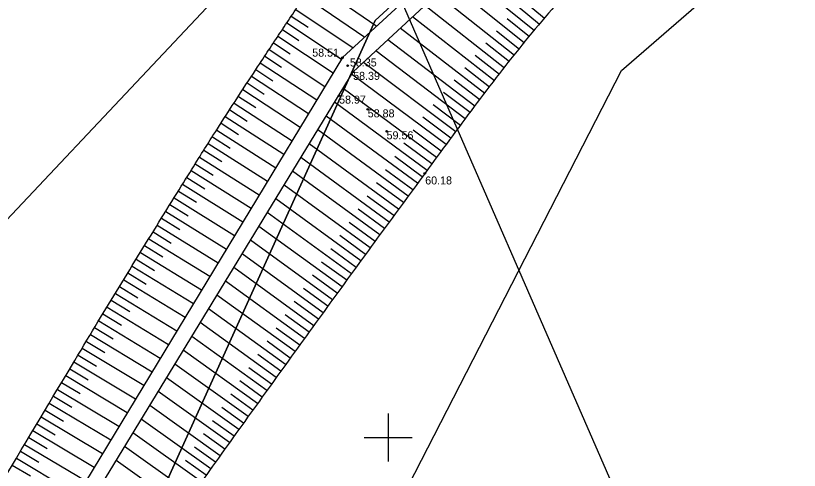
# Model space of a CAD drawing. Extents: x 616607 to 617499, y 408385 to 409695.
# Drawn here: x 616976.74 to 617025.68, y 408647.94 to 408676.32 of the extents above; entities that cross this region are included whole.
import ezdxf

# ---------------------------------------------------------------- set-up
doc = ezdxf.new("R2010")
doc.units = 0
for name, color, linetype in [('GEOD_ELEM_####_####_#', 7, 'Continuous'), ('HIDG_GRAV_####_####_#', 7, 'Continuous'), ('RAMI_PLAN_####_TKST_#', 7, 'Continuous'), ('RAMI_UZMR_####_####_#', 7, 'Continuous'), ('RELJ_AATZ_####_TKST_#', 7, 'Continuous'), ('RELJ_ELEM_####_####_#', 7, 'Continuous'), ('RELJ_NOGA_####_####_#', 7, 'Continuous'), ('ROBZ_IERR_####_####_#', 7, 'Continuous')]:
    doc.layers.add(name, color=color, linetype=linetype)

# ---------------------------------------------------------------- blocks, each defined once
blk = doc.blocks.new('PKT')
at = {"layer": 'RELJ_ELEM_####_####_#'}
blk.add_circle((0, 0), 0.05, dxfattribs=at)
blk = doc.blocks.new('KRUSTS')
at = {"layer": 'GEOD_ELEM_####_####_#'}
for p, q in [((0, 1.5), (0, 0)), ((-1.5, 0), (0, 0)), ((0, 0), (0, -1.5)), ((0, 0), (1.5, 0))]:
    blk.add_line(p, q, dxfattribs=at)

msp = doc.modelspace()

# ---------------------------------------------------------------- linework, layer by layer
at = {"layer": 'HIDG_GRAV_####_####_#'}
msp.add_lwpolyline([(616957.708, 408604.801), (616964.717, 408618.582), (616997.814, 408672.816), (617082.506, 408751.106), (617088.497, 408760.889), (617116.937, 408835.934), (617137.451, 408884.548), (617152.78, 408924.733), (617163.79, 408955.542), (617160.997, 408956.152), (617115.742, 408836.043), (617088.001, 408760.943), (617081.506, 408751.106), (616997.147, 408673.705), (616963.717, 408618.582), (616956.708, 408604.801)], dxfattribs=at)
at = {"layer": 'RAMI_PLAN_####_TKST_#'}
msp.add_line((616996.579, 408686.958), (617053.954, 408555.52), dxfattribs=at)
at = {"layer": 'RAMI_UZMR_####_####_#'}
for points in [[(617191.828, 409115.62), (617145.545, 408952.8), (617072.809, 408766.141), (616965.332, 408652.076), (616939.432, 408594.661), (616924.839, 408592.467), (616706.433, 408526.081), (616666.426, 408467.691)], [(616666.426, 408467.691), (616675.529, 408457.882), (616687.228, 408463.356), (616723.888, 408465.775), (616753.554, 408507.232), (616948.282, 408568.831), (616981.528, 408608.531), (617014.563, 408672.892), (617101.571, 408748.246), (617213.472, 409074.039)]]:
    msp.add_lwpolyline(points, dxfattribs=at)
at = {"layer": 'RELJ_NOGA_####_####_#'}
for p, q in [((617009.774, 408676.155), (617005.373, 408679.803)), ((617009.139, 408675.383), (617004.6, 408679.089)), ((616995.351, 408678.366), (616999.291, 408675.672)), ((617008.508, 408674.607), (617003.83, 408678.377)), ((616994.788, 408677.54), (616998.55, 408674.991)), ((617007.883, 408673.827), (617003.063, 408677.667)), ((616994.229, 408676.711), (616997.806, 408674.309)), ((617007.262, 408673.043), (617002.294, 408676.957)), ((617009.456, 408675.77), (617008.117, 408676.874)), ((616993.861, 408676.16), (616993.862, 408676.159)), ((616993.951, 408676.295), (616994.996, 408675.597)), ((617006.645, 408672.256), (617001.524, 408676.245)), ((617008.823, 408674.996), (617007.442, 408676.118)), ((616993.584, 408675.744), (616993.584, 408675.744)), ((616993.674, 408675.879), (616997.087, 408673.606)), ((616993.307, 408675.328), (616993.308, 408675.327)), ((616993.397, 408675.463), (616994.426, 408674.777)), ((617006.033, 408671.465), (617000.758, 408675.537)), ((617008.195, 408674.217), (617006.772, 408675.36)), ((616992.843, 408674.63), (616993.883, 408673.939)), ((616993.03, 408674.912), (616993.03, 408674.911)), ((616993.12, 408675.047), (616996.568, 408672.75)), ((617005.424, 408670.672), (616999.987, 408674.824)), ((617007.572, 408673.435), (617006.103, 408674.598)), ((616992.566, 408674.214), (616996.054, 408671.903)), ((616992.753, 408674.495), (616992.754, 408674.495)), ((617004.819, 408669.876), (616999.223, 408674.118)), ((616992.201, 408673.661), (616992.202, 408673.661)), ((616992.29, 408673.797), (616993.343, 408673.102)), ((616992.477, 408674.078), (616992.477, 408674.078)), ((617006.953, 408672.65), (617005.44, 408673.835)), ((616991.926, 408673.244), (616991.926, 408673.244)), ((616992.015, 408673.379), (616995.543, 408671.06)), ((617004.217, 408669.077), (616998.454, 408673.407)), ((616991.652, 408672.826), (616991.653, 408672.825)), ((616991.741, 408672.961), (616992.805, 408672.265)), ((617003.618, 408668.276), (616997.721, 408672.664)), ((617006.338, 408671.861), (617004.779, 408673.07)), ((616991.193, 408672.124), (616992.267, 408671.424)), ((616991.378, 408672.407), (616991.378, 408672.407)), ((616991.467, 408672.543), (616995.028, 408670.211)), ((617005.728, 408671.069), (617004.12, 408672.301)), ((616990.92, 408671.706), (616994.513, 408669.362)), ((616991.105, 408671.988), (616991.106, 408671.988)), ((617003.022, 408667.473), (616997.184, 408671.784)), ((616990.559, 408671.15), (616990.56, 408671.15)), ((616990.648, 408671.286), (616991.731, 408670.583)), ((616990.832, 408671.57), (616990.832, 408671.569)), ((617005.121, 408670.274), (617003.463, 408671.531)), ((616990.288, 408670.731), (616990.288, 408670.73)), ((616990.376, 408670.867), (616994.002, 408668.518)), ((617002.429, 408666.668), (616996.654, 408670.914)), ((617004.517, 408669.477), (617002.814, 408670.762)), ((616990.016, 408670.311), (616990.017, 408670.31)), ((616990.104, 408670.447), (616991.197, 408669.742)), ((616989.745, 408669.89), (616989.746, 408669.89)), ((616989.833, 408670.027), (616993.49, 408667.674)), ((617001.838, 408665.862), (616996.126, 408670.05)), ((617003.917, 408668.677), (617002.161, 408669.988)), ((616989.475, 408669.469), (616989.476, 408669.469)), ((616989.563, 408669.606), (616990.664, 408668.9)), ((617001.247, 408665.055), (616995.602, 408669.19)), ((616989.024, 408668.764), (616990.133, 408668.056)), ((616989.206, 408669.048), (616989.206, 408669.048)), ((616989.293, 408669.185), (616992.979, 408666.832)), ((617003.32, 408667.875), (617001.56, 408669.179)), ((616988.756, 408668.342), (616992.467, 408665.988)), ((616988.937, 408668.627), (616988.938, 408668.626)), ((617000.656, 408664.248), (616995.077, 408668.33)), ((617002.725, 408667.071), (617000.985, 408668.356)), ((616988.402, 408667.782), (616988.403, 408667.781)), ((616988.489, 408667.919), (616989.605, 408667.213)), ((616988.669, 408668.205), (616988.67, 408668.204)), ((616988.136, 408667.359), (616988.136, 408667.359)), ((616988.222, 408667.496), (616991.955, 408665.144)), ((617000.066, 408663.441), (616994.551, 408667.468)), ((617002.133, 408666.265), (617000.41, 408667.529)), ((616987.87, 408666.935), (616987.871, 408666.935)), ((616987.956, 408667.073), (616989.081, 408666.37)), ((616987.605, 408666.511), (616987.606, 408666.511)), ((616987.691, 408666.649), (616991.449, 408664.308)), ((616999.476, 408662.633), (616994.028, 408666.612)), ((617001.542, 408665.458), (616999.838, 408666.706)), ((616987.162, 408665.8), (616990.933, 408663.458)), ((616987.341, 408666.087), (616987.342, 408666.086)), ((616987.427, 408666.224), (616988.556, 408665.521)), ((617000.951, 408664.651), (616999.267, 408665.883)), ((616986.899, 408665.375), (616988.031, 408664.672)), ((616987.077, 408665.662), (616987.077, 408665.662)), ((616998.887, 408661.825), (616993.503, 408665.752)), ((616986.55, 408664.812), (616986.55, 408664.812)), ((616986.635, 408664.951), (616990.416, 408662.606)), ((616986.813, 408665.237), (616986.814, 408665.237)), ((616998.298, 408661.017), (616992.979, 408664.892)), ((617000.361, 408663.844), (616998.697, 408665.061)), ((616986.287, 408664.387), (616986.287, 408664.387)), ((616986.371, 408664.526), (616987.507, 408663.821)), ((616986.024, 408663.962), (616986.024, 408663.962)), ((616986.108, 408664.1), (616989.9, 408661.754)), ((616997.709, 408660.209), (616992.454, 408664.033)), ((616999.771, 408663.037), (616998.127, 408664.238)), ((616985.761, 408663.536), (616985.762, 408663.536)), ((616985.845, 408663.675), (616986.985, 408662.972)), ((616999.181, 408662.229), (616997.556, 408663.414)), ((616985.499, 408663.111), (616985.499, 408663.111)), ((616985.583, 408663.25), (616989.384, 408660.904)), ((616997.121, 408659.4), (616991.93, 408663.173)), ((616985.058, 408662.399), (616988.868, 408660.053)), ((616985.236, 408662.685), (616985.237, 408662.685)), ((616985.32, 408662.824), (616986.461, 408662.12)), ((616998.592, 408661.421), (616996.987, 408662.591)), ((616984.796, 408661.973), (616985.94, 408661.269)), ((616984.975, 408662.259), (616984.975, 408662.259)), ((616996.533, 408658.591), (616991.407, 408662.317)), ((616984.452, 408661.407), (616984.452, 408661.407)), ((616984.534, 408661.547), (616988.351, 408659.201)), ((616984.713, 408661.833), (616984.714, 408661.832)), ((616995.946, 408657.782), (616990.882, 408661.457)), ((616998.003, 408660.613), (616996.418, 408661.768)), ((616984.19, 408660.98), (616984.191, 408660.98)), ((616984.273, 408661.12), (616985.419, 408660.417)), ((616997.415, 408659.804), (616995.848, 408660.944)), ((616983.93, 408660.554), (616983.93, 408660.554)), ((616984.011, 408660.694), (616987.837, 408658.354)), ((616995.358, 408656.972), (616990.358, 408660.598)), ((616983.669, 408660.127), (616983.67, 408660.127)), ((616983.75, 408660.268), (616984.899, 408659.565)), ((616996.827, 408658.995), (616995.279, 408660.12)), ((616983.229, 408659.414), (616984.379, 408658.713)), ((616983.408, 408659.7), (616983.409, 408659.7)), ((616983.49, 408659.841), (616987.322, 408657.504)), ((616994.771, 408656.163), (616989.835, 408659.741)), ((616982.969, 408658.987), (616986.803, 408656.649)), ((616983.148, 408659.273), (616983.149, 408659.273)), ((616996.239, 408658.186), (616994.711, 408659.296)), ((616982.709, 408658.56), (616983.86, 408657.86)), ((616982.888, 408658.846), (616982.888, 408658.846)), ((616994.185, 408655.353), (616989.31, 408658.881)), ((616995.652, 408657.377), (616994.142, 408658.472)), ((616982.369, 408657.992), (616982.369, 408657.992)), ((616982.449, 408658.133), (616986.289, 408655.8)), ((616982.628, 408658.419), (616982.629, 408658.419)), ((616993.598, 408654.543), (616988.788, 408658.025)), ((616982.109, 408657.564), (616982.11, 408657.564)), ((616982.19, 408657.705), (616983.342, 408657.007)), ((616995.065, 408656.568), (616993.574, 408657.648)), ((616981.85, 408657.137), (616981.85, 408657.137)), ((616981.93, 408657.278), (616985.772, 408654.948)), ((616993.013, 408653.732), (616988.263, 408657.164)), ((616981.591, 408656.709), (616981.592, 408656.709)), ((616981.672, 408656.85), (616982.825, 408656.152)), ((616994.478, 408655.758), (616993.006, 408656.823)), ((616981.154, 408655.994), (616982.308, 408655.298)), ((616981.332, 408656.281), (616981.332, 408656.281)), ((616981.413, 408656.422), (616985.258, 408654.1)), ((616992.428, 408652.921), (616987.737, 408656.303)), ((616993.892, 408654.948), (616992.439, 408655.999)), ((616980.896, 408655.566), (616984.741, 408653.249)), ((616981.073, 408655.854), (616981.074, 408655.853)), ((616980.557, 408654.997), (616980.557, 408654.997)), ((616980.638, 408655.138), (616981.792, 408654.444)), ((616980.815, 408655.426), (616980.815, 408655.425)), ((616991.843, 408652.11), (616987.209, 408655.439)), ((616993.305, 408654.138), (616991.871, 408655.174)), ((616980.298, 408654.569), (616980.299, 408654.569)), ((616980.381, 408654.709), (616984.225, 408652.397)), ((616991.26, 408651.297), (616986.685, 408654.579)), ((616980.04, 408654.141), (616980.041, 408654.14)), ((616980.123, 408654.281), (616981.277, 408653.589)), ((616992.72, 408653.327), (616991.303, 408654.348)), ((616979.782, 408653.713), (616979.783, 408653.713)), ((616979.866, 408653.852), (616983.709, 408651.547)), ((616990.678, 408650.485), (616986.161, 408653.72)), ((616979.525, 408653.284), (616979.526, 408653.284)), ((616979.609, 408653.423), (616980.762, 408652.733)), ((616992.135, 408652.516), (616990.737, 408653.522)), ((616979.095, 408652.565), (616980.247, 408651.876)), ((616979.267, 408652.856), (616979.267, 408652.855)), ((616979.352, 408652.994), (616983.192, 408650.695)), ((616990.096, 408649.671), (616985.636, 408652.86)), ((616991.552, 408651.704), (616990.171, 408652.696)), ((616978.838, 408652.136), (616982.674, 408649.84)), ((616979.01, 408652.427), (616979.01, 408652.427)), ((616978.582, 408651.707), (616979.732, 408651.019)), ((616978.752, 408651.999), (616978.752, 408651.998)), ((616989.515, 408648.857), (616985.111, 408652)), ((616990.969, 408650.891), (616989.605, 408651.868)), ((616978.237, 408651.141), (616978.238, 408651.141)), ((616978.325, 408651.278), (616982.157, 408648.987)), ((616978.495, 408651.57), (616978.496, 408651.569)), ((616988.934, 408648.043), (616984.586, 408651.14)), ((616977.98, 408650.712), (616977.981, 408650.712)), ((616978.069, 408650.849), (616979.217, 408650.162)), ((616990.387, 408650.078), (616989.04, 408651.041)), ((616977.723, 408650.284), (616977.723, 408650.283)), ((616977.812, 408650.42), (616981.638, 408648.132)), ((616988.354, 408647.228), (616984.062, 408650.281)), ((616989.805, 408649.264), (616988.475, 408650.213)), ((616977.466, 408649.855), (616977.467, 408649.854)), ((616977.556, 408649.99), (616978.703, 408649.305)), ((616977.043, 408649.132), (616978.188, 408648.448)), ((616977.209, 408649.426), (616977.209, 408649.426)), ((616977.299, 408649.561), (616981.121, 408647.279)), ((616987.775, 408646.413), (616983.538, 408649.422)), ((616989.224, 408648.45), (616987.912, 408649.387)), ((616976.786, 408648.703), (616980.603, 408646.425)), ((616976.952, 408648.997), (616976.953, 408648.996)), ((616976.53, 408648.273), (616977.674, 408647.59)), ((616987.196, 408645.598), (616983.014, 408648.564)), ((616988.644, 408647.636), (616987.348, 408648.558))]:
    msp.add_line(p, q, dxfattribs=at)
for points in [[(616952.11, 408607.531), (616956.151, 408614.166), (616960.13, 408620.838), (616964.128, 408627.499), (616969.357, 408636.209), (616974.533, 408644.951), (616979.755, 408653.666), (616982.367, 408658.027), (616985.018, 408662.364), (616987.709, 408666.677), (616989.056, 408668.838), (616990.438, 408670.976), (616991.835, 408673.105), (616992.534, 408674.172), (616993.243, 408675.231), (616993.95, 408676.293), (616994.657, 408677.356), (616995.377, 408678.409), (616996.104, 408679.46), (616998.164, 408682.436), (617000.493, 408685.215), (617003.037, 408687.806), (617005.59, 408690.406), (617008.236, 408692.879), (617011.016, 408695.214), (617013.812, 408697.562), (617016.632, 408699.88), (617019.423, 408702.233), (617020.817, 408703.408), (617022.221, 408704.57), (617023.595, 408705.77), (617024.962, 408706.965), (617026.3, 408708.194), (617027.642, 408709.417), (617031.797, 408713.202), (617035.92, 408717.024), (617040.083, 408720.8), (617044.243, 408724.572), (617048.471, 408728.267), (617052.642, 408732.025), (617056.824, 408735.794), (617060.981, 408739.59), (617065.093, 408743.436), (617067.159, 408745.369), (617069.191, 408747.335), (617071.208, 408749.318), (617072.22, 408750.314), (617073.221, 408751.32), (617074.226, 408752.322), (617075.234, 408753.328), (617076.23, 408754.338), (617077.212, 408755.375), (617081.698, 408760.112), (617084.989, 408765.985), (617087.243, 408772.093), (617089.541, 408778.321), (617091.528, 408784.634), (617093.829, 408790.846), (617099.646, 408806.547), (617105.384, 408822.279), (617111.331, 408837.932), (617116.967, 408852.766), (617122.795, 408867.526), (617128.465, 408882.346), (617134.52, 408898.17), (617140.109, 408914.165), (617146.15, 408930), (617147.203, 408932.762), (617148.413, 408935.46), (617149.608, 408938.162), (617150.805, 408940.87), (617152.218, 408943.437), (617153.491, 408946.151), (617155.134, 408949.654), (617156.252, 408953.338), (617157.386, 408956.937), (617157.388, 408956.942), (617157.376, 408956.956), (617157.382, 408956.955), (617158.587, 408956.687), (617159.792, 408956.42), (617160.997, 408956.152)], [(617163.79, 408955.542), (617165.45, 408955.194), (617167.11, 408954.846), (617168.77, 408954.498), (617168.913, 408954.468), (617169.034, 408954.324), (617169.074, 408954.183), (617169.128, 408953.99), (617169.08, 408953.773), (617169.007, 408953.587), (617168.835, 408953.148), (617168.665, 408952.708), (617168.483, 408952.272), (617167.485, 408949.894), (617166.495, 408947.512), (617165.486, 408945.138), (617164.477, 408942.762), (617163.444, 408940.395), (617162.435, 408938.019), (617160.416, 408933.265), (617158.392, 408928.513), (617156.542, 408923.692), (617150.713, 408908.507), (617144.931, 408893.305), (617139.111, 408878.118), (617136.201, 408870.523), (617133.294, 408862.928), (617130.378, 408855.336), (617127.463, 408847.744), (617124.504, 408840.168), (617121.547, 408832.592), (617116.624, 408819.98), (617111.621, 408807.399), (617106.663, 408794.801), (617101.918, 408782.741), (617097.386, 408770.604), (617092.68, 408758.522), (617091.748, 408756.128), (617090.638, 408753.8), (617089.099, 408751.701), (617087.891, 408750.055), (617086.512, 408748.607), (617085.075, 408747.191), (617082.094, 408744.254), (617079.138, 408741.303), (617076.078, 408738.453), (617073.02, 408735.605), (617069.97, 408732.751), (617066.861, 408729.96), (617060.644, 408724.38), (617054.349, 408718.89), (617048.124, 408713.32), (617041.902, 408707.753), (617035.717, 408702.149), (617029.576, 408696.491), (617026.506, 408693.662), (617023.563, 408690.704), (617020.596, 408687.763), (617017.626, 408684.818), (617014.683, 408681.855), (617011.931, 408678.697), (617008.517, 408674.776), (617005.359, 408670.661), (617002.288, 408666.476), (616999.318, 408662.428), (616996.36, 408658.374), (616993.424, 408654.302), (616990.492, 408650.235), (616987.575, 408646.161), (616984.691, 408642.059), (616983.288, 408640.063), (616981.951, 408638.02), (616980.703, 408635.922), (616979.453, 408633.819), (616978.237, 408631.7), (616977.033, 408629.572), (616975.83, 408627.444), (616974.65, 408625.305), (616973.452, 408623.174), (616972.259, 408621.052), (616970.984, 408618.974), (616969.729, 408616.893), (616969.613, 408616.701), (616969.41, 408616.592), (616969.29, 408616.383), (616968.995, 408615.872), (616968.948, 408615.291), (616969.02, 408614.761), (616969.09, 408614.251), (616969.19, 408613.683), (616969.493, 408613.251)]]:
    msp.add_open_spline(points, degree=3, dxfattribs=at)
at = {"layer": 'ROBZ_IERR_####_####_#'}
for points in [[(617055.284, 408797.783), (617087.528, 408757.04), (616999.181, 408676.019), (616968.565, 408608.405), (616958.517, 408604.593), (616940.576, 408582.801), (616889.795, 408568.012), (616805.459, 408543.657), (616730.494, 408522.344), (616717.135, 408556.579)], [(617001.984, 408630.998), (616968.565, 408608.405), (616999.181, 408676.019), (617087.528, 408757.04), (617055.515, 408797.492)]]:
    msp.add_lwpolyline(points, dxfattribs=at)

# ---------------------------------------------------------------- block references
at = {"layer": 'GEOD_ELEM_####_####_#'}
msp.add_blockref('KRUSTS', (617000, 408650), dxfattribs=at)
at = {"layer": 'RELJ_ELEM_####_####_#'}
for p in [(616997.147, 408673.705), (616997.472, 408673.198), (616997.814, 408672.816), (616996.937, 408671.332), (616998.725, 408670.476), (616999.903, 408669.106), (617002.288, 408666.476)]:
    msp.add_blockref('PKT', p, dxfattribs=at)

# ---------------------------------------------------------------- texts
at = {"layer": 'RELJ_AATZ_####_TKST_#'}
for s, p in [('58.51', (616995.259, 408673.766)), ('58.35', (616997.612, 408673.153)), ('58.39', (616997.814, 408672.316)), ('58.97', (616996.937, 408670.832)), ('58.88', (616998.725, 408669.976)), ('59.56', (616999.903, 408668.606)), ('60.18', (617002.314, 408665.788))]:
    msp.add_text(s, height=0.5, dxfattribs=at).set_placement(p)

doc.saveas('drawing.dxf')
